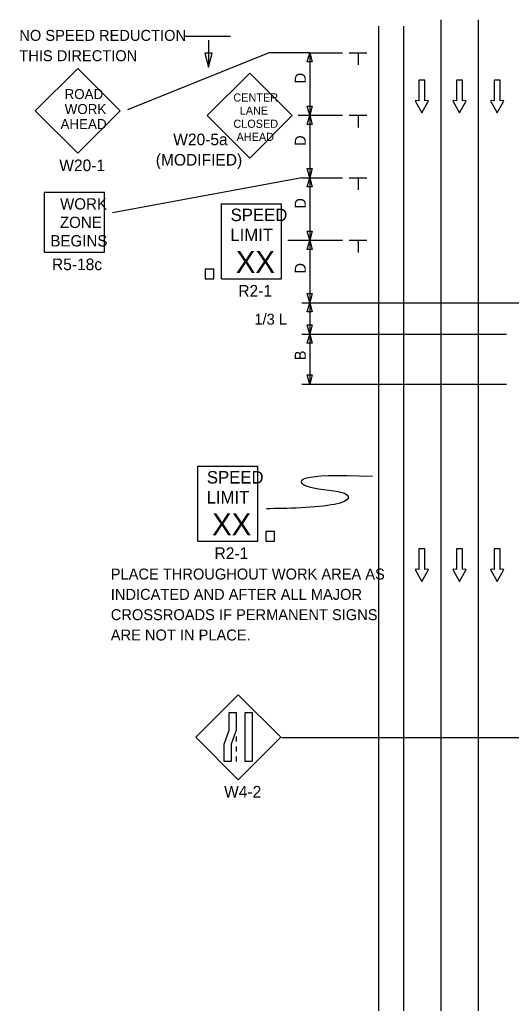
# Model space of a CAD drawing. Extents: x 16732 to 18475, y 5726 to 6929.
# Drawn here: x 16732 to 17046, y 6300 to 6929 of the extents above; entities that cross this region are included whole.
import ezdxf

# ---------------------------------------------------------------- set-up
doc = ezdxf.new("R2010")
doc.units = 0
for name, color, linetype in [('ALI_LEGAL_EX', 7, 'Continuous'), ('MT_SCRATCH_LEVEL_E', 7, 'Continuous'), ('PAVT_EDGE_EX', 7, 'Continuous'), ('TRAFFIC_SIGNS_PR', 7, 'Continuous'), ('TYPICAL_TEXT_DIMEN_PR', 7, 'Continuous')]:
    doc.layers.add(name, color=color, linetype=linetype)

msp = doc.modelspace()

# ---------------------------------------------------------------- linework, layer by layer
at = {"layer": 'ALI_LEGAL_EX'}
for p, q in [((17001.36, 6131.68), (17001.36, 6928.96)), ((17025.36, 6131.68), (17025.36, 6928.96))]:
    msp.add_line(p, q, dxfattribs=at)
for points in [[(17001.36, 6831.68), (17001.36, 6856.68)], [(17025.36, 6831.68), (17025.36, 6856.68)], [(17001.36, 6731.68), (17001.36, 6756.68)], [(17025.36, 6731.68), (17025.36, 6756.68)], [(17001.36, 6631.68), (17001.36, 6656.68)], [(17025.36, 6631.68), (17025.36, 6656.68)], [(17001.36, 6531.68), (17001.36, 6556.68)], [(17025.36, 6531.68), (17025.36, 6556.68)], [(17001.36, 6431.68), (17001.36, 6456.68)], [(17025.36, 6431.68), (17025.36, 6456.68)], [(17001.36, 6331.68), (17001.36, 6356.68)], [(17025.36, 6331.68), (17025.36, 6356.68)]]:
    msp.add_lwpolyline(points, dxfattribs=at)
at = {"layer": 'MT_SCRATCH_LEVEL_E'}
for p, q in [((16990.96, 6890.26), (16987.21, 6890.26)), ((16987.21, 6890.26), (16987.21, 6877.01)), ((16990.96, 6890.26), (16987.21, 6890.26)), ((16987.21, 6890.26), (16987.21, 6877.01)), ((16990.96, 6877.01), (16990.96, 6890.26)), ((16990.96, 6877.01), (16990.96, 6890.26)), ((17015.03, 6890.26), (17011.28, 6890.26)), ((17011.28, 6890.26), (17011.28, 6877.01)), ((17015.03, 6890.26), (17011.28, 6890.26)), ((17011.28, 6890.26), (17011.28, 6877.01)), ((17015.03, 6877.01), (17015.03, 6890.26)), ((17015.03, 6877.01), (17015.03, 6890.26)), ((17039.1, 6890.26), (17035.35, 6890.26)), ((17035.35, 6890.26), (17035.35, 6877.01)), ((17039.1, 6890.26), (17035.35, 6890.26)), ((17035.35, 6890.26), (17035.35, 6877.01)), ((17039.1, 6877.01), (17039.1, 6890.26)), ((17039.1, 6877.01), (17039.1, 6890.26)), ((16984.96, 6876.64), (16989.1, 6869.4)), ((16984.96, 6876.64), (16989.1, 6869.4)), ((16987.21, 6877.01), (16985.44, 6877.32)), ((16987.21, 6877.01), (16985.44, 6877.32)), ((16989.1, 6869.4), (16993.21, 6876.64)), ((16989.1, 6869.4), (16993.21, 6876.64)), ((16992.73, 6877.32), (16990.96, 6877.01)), ((16992.73, 6877.32), (16990.96, 6877.01)), ((17009.03, 6876.64), (17013.17, 6869.4)), ((17009.03, 6876.64), (17013.17, 6869.4)), ((17011.28, 6877.01), (17009.51, 6877.32)), ((17011.28, 6877.01), (17009.51, 6877.32)), ((17013.17, 6869.4), (17017.28, 6876.64)), ((17013.17, 6869.4), (17017.28, 6876.64)), ((17016.8, 6877.32), (17015.03, 6877.01)), ((17016.8, 6877.32), (17015.03, 6877.01)), ((17033.1, 6876.64), (17037.24, 6869.4)), ((17033.1, 6876.64), (17037.24, 6869.4)), ((17035.35, 6877.01), (17033.58, 6877.32)), ((17035.35, 6877.01), (17033.58, 6877.32)), ((17037.24, 6869.4), (17041.36, 6876.64)), ((17037.24, 6869.4), (17041.36, 6876.64)), ((17040.87, 6877.32), (17039.1, 6877.01)), ((17040.87, 6877.32), (17039.1, 6877.01)), ((16990.96, 6590.35), (16987.21, 6590.35)), ((16987.21, 6590.35), (16987.21, 6577.09)), ((16990.96, 6590.35), (16987.21, 6590.35)), ((16987.21, 6590.35), (16987.21, 6577.09)), ((16990.96, 6577.09), (16990.96, 6590.35)), ((16990.96, 6577.09), (16990.96, 6590.35)), ((17015.03, 6590.35), (17011.28, 6590.35)), ((17011.28, 6590.35), (17011.28, 6577.09)), ((17015.03, 6590.35), (17011.28, 6590.35)), ((17011.28, 6590.35), (17011.28, 6577.09)), ((17015.03, 6577.09), (17015.03, 6590.35)), ((17015.03, 6577.09), (17015.03, 6590.35)), ((17039.1, 6590.35), (17035.35, 6590.35)), ((17035.35, 6590.35), (17035.35, 6577.09)), ((17039.1, 6590.35), (17035.35, 6590.35)), ((17035.35, 6590.35), (17035.35, 6577.09)), ((17039.1, 6577.09), (17039.1, 6590.35)), ((17039.1, 6577.09), (17039.1, 6590.35)), ((16984.96, 6576.72), (16989.1, 6569.48)), ((16984.96, 6576.72), (16989.1, 6569.48)), ((16987.21, 6577.09), (16985.44, 6577.4)), ((16987.21, 6577.09), (16985.44, 6577.4)), ((16989.1, 6569.48), (16993.21, 6576.72)), ((16989.1, 6569.48), (16993.21, 6576.72)), ((16992.73, 6577.4), (16990.96, 6577.09)), ((16992.73, 6577.4), (16990.96, 6577.09)), ((17009.03, 6576.72), (17013.17, 6569.48)), ((17009.03, 6576.72), (17013.17, 6569.48)), ((17011.28, 6577.09), (17009.51, 6577.4)), ((17011.28, 6577.09), (17009.51, 6577.4)), ((17013.17, 6569.48), (17017.28, 6576.72)), ((17013.17, 6569.48), (17017.28, 6576.72)), ((17016.8, 6577.4), (17015.03, 6577.09)), ((17016.8, 6577.4), (17015.03, 6577.09)), ((17033.1, 6576.72), (17037.24, 6569.48)), ((17033.1, 6576.72), (17037.24, 6569.48)), ((17035.35, 6577.09), (17033.58, 6577.4)), ((17035.35, 6577.09), (17033.58, 6577.4)), ((17037.24, 6569.48), (17041.36, 6576.72)), ((17037.24, 6569.48), (17041.36, 6576.72)), ((17040.87, 6577.4), (17039.1, 6577.09)), ((17040.87, 6577.4), (17039.1, 6577.09))]:
    msp.add_line(p, q, dxfattribs=at)
for centre, start, end in [((16985.37, 6876.86), 80.03619, 209.77312), ((16985.37, 6876.86), 80.03619, 209.77312), ((16992.81, 6876.86), 330.42484, 99.96381), ((16992.81, 6876.86), 330.42484, 99.96381), ((17009.44, 6876.86), 80.03619, 209.77312), ((17009.44, 6876.86), 80.03619, 209.77312), ((17016.88, 6876.86), 330.42484, 99.96381), ((17016.88, 6876.86), 330.42484, 99.96381), ((17033.51, 6876.86), 80.03619, 209.77312), ((17033.51, 6876.86), 80.03619, 209.77312), ((17040.95, 6876.86), 330.42484, 99.96381), ((17040.95, 6876.86), 330.42484, 99.96381), ((16985.37, 6576.94), 80.03619, 209.77312), ((16985.37, 6576.94), 80.03619, 209.77312), ((16992.81, 6576.94), 330.42484, 99.96381), ((16992.81, 6576.94), 330.42484, 99.96381), ((17009.44, 6576.94), 80.03619, 209.77312), ((17009.44, 6576.94), 80.03619, 209.77312), ((17016.88, 6576.94), 330.42484, 99.96381), ((17016.88, 6576.94), 330.42484, 99.96381), ((17033.51, 6576.94), 80.03619, 209.77312), ((17033.51, 6576.94), 80.03619, 209.77312), ((17040.95, 6576.94), 330.42484, 99.96381), ((17040.95, 6576.94), 330.42484, 99.96381)]:
    msp.add_arc(centre, 0.463, start, end, dxfattribs=at)
at = {"layer": 'PAVT_EDGE_EX'}
for p, q in [((16961.36, 6924.76), (16961.36, 6059.7)), ((16977.36, 6924.76), (16977.36, 6059.7))]:
    msp.add_line(p, q, dxfattribs=at)
at = {"layer": 'TRAFFIC_SIGNS_PR'}
for p, q in [((16768.98, 6897.78), (16741.83, 6870.62)), ((16796.13, 6870.62), (16768.98, 6897.78)), ((16878.95, 6894.71), (16851.79, 6867.56)), ((16906.1, 6867.56), (16878.95, 6894.71)), ((16741.83, 6870.62), (16768.98, 6843.47)), ((16768.98, 6843.47), (16796.13, 6870.62)), ((16851.79, 6867.56), (16878.95, 6840.4)), ((16878.95, 6840.4), (16906.1, 6867.56)), ((16747.67, 6780.11), (16747.67, 6818.51)), ((16747.67, 6818.51), (16786.07, 6818.51)), ((16786.07, 6780.11), (16786.07, 6818.51)), ((16860.99, 6811.18), (16899.39, 6811.18)), ((16860.99, 6763.18), (16860.99, 6811.18)), ((16899.39, 6763.18), (16899.39, 6811.18)), ((16747.67, 6780.11), (16786.07, 6780.11)), ((16860.99, 6763.18), (16899.39, 6763.18)), ((16845.79, 6643.28), (16884.19, 6643.28)), ((16845.79, 6595.28), (16845.79, 6643.28)), ((16884.19, 6595.28), (16884.19, 6643.28)), ((16845.79, 6595.28), (16884.19, 6595.28)), ((16871.63, 6496.94), (16844.48, 6469.78)), ((16898.78, 6469.78), (16871.63, 6496.94)), ((16844.48, 6469.78), (16871.63, 6442.63)), ((16870.38, 6470.27), (16870.38, 6467.07)), ((16871.63, 6442.63), (16898.78, 6469.78)), ((16870.38, 6463.87), (16870.38, 6460.67)), ((16870.38, 6457.47), (16870.38, 6454.27))]:
    msp.add_line(p, q, dxfattribs=at)
for points in [[(16850.38, 6763.18), (16855.98, 6763.18), (16855.98, 6769.35), (16850.38, 6769.35)], [(16889.21, 6595.28), (16894.8, 6595.28), (16894.8, 6601.46), (16889.21, 6601.46)], [(16870.38, 6485.52), (16870.38, 6474.34), (16867.04, 6465.46), (16867.04, 6454.27), (16862.55, 6454.27), (16862.55, 6465.46), (16865.89, 6474.34), (16865.89, 6485.52)], [(16880.52, 6485.52), (16880.52, 6454.27), (16876.03, 6454.27), (16876.03, 6485.52)]]:
    msp.add_lwpolyline(points, close=True, dxfattribs=at)
at = {"layer": 'TYPICAL_TEXT_DIMEN_PR'}
for p, q in [((16866.78, 6918.28), (16837.35, 6918.28)), ((16852.61, 6915.78), (16852.61, 6898.66)), ((16800.92, 6871.57), (16890.94, 6907.8)), ((16852.61, 6907.45), (16850.25, 6907.45)), ((16850.25, 6907.45), (16852.61, 6898.66)), ((16852.61, 6898.66), (16854.97, 6907.45)), ((16854.97, 6907.45), (16852.61, 6907.45)), ((16917.36, 6907.8), (16890.94, 6907.8)), ((16915.79, 6901.94), (16917.36, 6907.8)), ((16917.36, 6907.8), (16917.36, 6867.8)), ((16917.36, 6907.8), (16918.93, 6901.94)), ((16917.36, 6907.8), (16938.36, 6907.8)), ((16942.61, 6907.8), (16953.86, 6907.8)), ((16948.23, 6907.8), (16948.23, 6900.02)), ((16917.36, 6901.94), (16915.79, 6901.94)), ((16918.93, 6901.94), (16917.36, 6901.94)), ((16917.36, 6867.8), (16915.79, 6873.66)), ((16915.79, 6873.66), (16917.36, 6873.66)), ((16917.36, 6873.66), (16918.93, 6873.66)), ((16918.93, 6873.66), (16917.36, 6867.8)), ((16909.94, 6867.8), (16938.36, 6867.8)), ((16915.79, 6861.94), (16917.36, 6867.8)), ((16917.36, 6867.8), (16917.36, 6827.8)), ((16917.36, 6867.8), (16918.93, 6861.94)), ((16942.61, 6867.8), (16953.86, 6867.8)), ((16948.23, 6867.8), (16948.23, 6860.02)), ((16917.36, 6861.94), (16915.79, 6861.94)), ((16918.93, 6861.94), (16917.36, 6861.94)), ((16917.36, 6827.8), (16915.79, 6833.66)), ((16915.79, 6833.66), (16917.36, 6833.66)), ((16917.36, 6833.66), (16918.93, 6833.66)), ((16918.93, 6833.66), (16917.36, 6827.8)), ((16912.36, 6827.8), (16791.29, 6805.37)), ((16912.36, 6827.8), (16938.36, 6827.8)), ((16915.79, 6821.94), (16917.36, 6827.8)), ((16917.36, 6827.8), (16917.36, 6787.8)), ((16917.36, 6827.8), (16918.93, 6821.94)), ((16942.61, 6827.8), (16953.86, 6827.8)), ((16948.23, 6827.8), (16948.23, 6820.02)), ((16917.36, 6821.94), (16915.79, 6821.94)), ((16918.93, 6821.94), (16917.36, 6821.94)), ((16917.36, 6787.8), (16915.79, 6793.66)), ((16915.79, 6793.66), (16917.36, 6793.66)), ((16917.36, 6793.66), (16918.93, 6793.66)), ((16918.93, 6793.66), (16917.36, 6787.8)), ((16903.41, 6787.8), (16938.36, 6787.8)), ((16915.79, 6781.94), (16917.36, 6787.8)), ((16917.36, 6787.8), (16918.93, 6781.94)), ((16917.36, 6787.8), (16917.36, 6747.8)), ((16942.61, 6787.8), (16953.86, 6787.8)), ((16948.23, 6787.8), (16948.23, 6780.02)), ((16917.36, 6781.94), (16915.79, 6781.94)), ((16918.93, 6781.94), (16917.36, 6781.94)), ((16912.36, 6747.8), (17063.81, 6747.8)), ((16917.36, 6747.8), (16915.79, 6753.66)), ((16915.79, 6753.66), (16917.36, 6753.66)), ((16915.79, 6741.94), (16917.36, 6747.8)), ((16917.36, 6753.66), (16918.93, 6753.66)), ((16918.93, 6753.66), (16917.36, 6747.8)), ((16917.36, 6747.8), (16917.36, 6727.81)), ((16917.36, 6747.8), (16918.93, 6741.94)), ((16917.36, 6741.94), (16915.79, 6741.94)), ((16918.93, 6741.94), (16917.36, 6741.94)), ((16917.36, 6727.81), (16915.79, 6733.67)), ((16915.79, 6733.67), (16917.36, 6733.67)), ((16917.36, 6733.67), (16918.93, 6733.67)), ((16918.93, 6733.67), (16917.36, 6727.81)), ((16912.36, 6727.81), (17043.23, 6727.81)), ((16915.79, 6721.95), (16917.36, 6727.81)), ((16917.36, 6727.81), (16917.36, 6695.75)), ((16917.36, 6727.81), (16918.93, 6721.95)), ((16917.36, 6721.95), (16915.79, 6721.95)), ((16918.93, 6721.95), (16917.36, 6721.95)), ((16917.36, 6695.75), (16915.79, 6701.61)), ((16915.79, 6701.61), (16917.36, 6701.61)), ((16917.36, 6701.61), (16918.93, 6701.61)), ((16918.93, 6701.61), (16917.36, 6695.75)), ((16912.36, 6695.75), (17043.23, 6695.75)), ((17075.07, 6469.39), (16899.36, 6469.39))]:
    msp.add_line(p, q, dxfattribs=at)
msp.add_open_spline([(16957.5, 6636.6), (16908.59, 6638.89), (16908.59, 6628.28), (16943.93, 6628.28), (16943.93, 6617.27), (16901.07, 6616.02), (16889.72, 6616.04)], degree=3, dxfattribs=at)

# ---------------------------------------------------------------- texts
at = {"layer": 'TRAFFIC_SIGNS_PR'}
for s, height, p in [('ROAD', 6.4, (16760.52, 6878.16)), ('CENTER', 5.2, (16868.52, 6876.56)), ('WORK', 6.4, (16760.63, 6868.56)), ('LANE', 5.2, (16872.6, 6868.16)), ('AHEAD', 6.4, (16757.94, 6858.96)), ('CLOSED', 5.2, (16868.53, 6859.76)), ('W20-5a', 7.44, (16830.04, 6848.61)), ('AHEAD', 5.2, (16870.55, 6851.36)), ('(MODIFIED)', 7.44, (16818.89, 6835.57)), ('W20-1', 7.44, (16757.15, 6832.03)), ('WORK', 7.217, (16757.66, 6807.47)), ('SPEED', 8, (16866.76, 6800.04)), ('ZONE', 7.217, (16757.55, 6795.66)), ('LIMIT', 8, (16866.6, 6787.24)), ('BEGINS', 7.217, (16751.47, 6783.85)), ('XX', 14.031, (16870.11, 6766.93)), ('R5-18c', 7.44, (16752.48, 6768.67)), ('R2-1', 7.44, (16871.67, 6751.74)), ('SPEED', 8, (16851.56, 6632.15)), ('LIMIT', 8, (16851.4, 6619.35)), ('XX', 14.031, (16854.91, 6599.04)), ('R2-1', 7.44, (16856.47, 6583.84)), ('PLACE THROUGHOUT WORK AREA AS', 7, (16790.11, 6570.71)), ('INDICATED AND AFTER ALL MAJOR', 7, (16790.11, 6557.71)), ('CROSSROADS IF PERMANENT SIGNS', 7, (16790.11, 6544.71)), ('ARE NOT IN PLACE.', 7, (16790.11, 6531.71)), ('W4-2', 7.44, (16862.59, 6431.19))]:
    msp.add_text(s, height=height, dxfattribs=at).set_placement(p)
at = {"layer": 'TYPICAL_TEXT_DIMEN_PR'}
for s, p in [('NO SPEED REDUCTION', (16731.62, 6915.4)), ('THIS DIRECTION', (16731.62, 6902.4)), ('1/3 L', (16881.99, 6733.81))]:
    msp.add_text(s, height=7, dxfattribs=at).set_placement(p)
for s, p in [('D', (16914.8, 6888.17)), ('D', (16914.8, 6848.17)), ('D', (16914.8, 6808.02)), ('D', (16914.8, 6766.47)), ('B', (16914.8, 6711.01))]:
    msp.add_text(s, height=7, rotation=90, dxfattribs=at).set_placement(p)

doc.saveas('drawing.dxf')
